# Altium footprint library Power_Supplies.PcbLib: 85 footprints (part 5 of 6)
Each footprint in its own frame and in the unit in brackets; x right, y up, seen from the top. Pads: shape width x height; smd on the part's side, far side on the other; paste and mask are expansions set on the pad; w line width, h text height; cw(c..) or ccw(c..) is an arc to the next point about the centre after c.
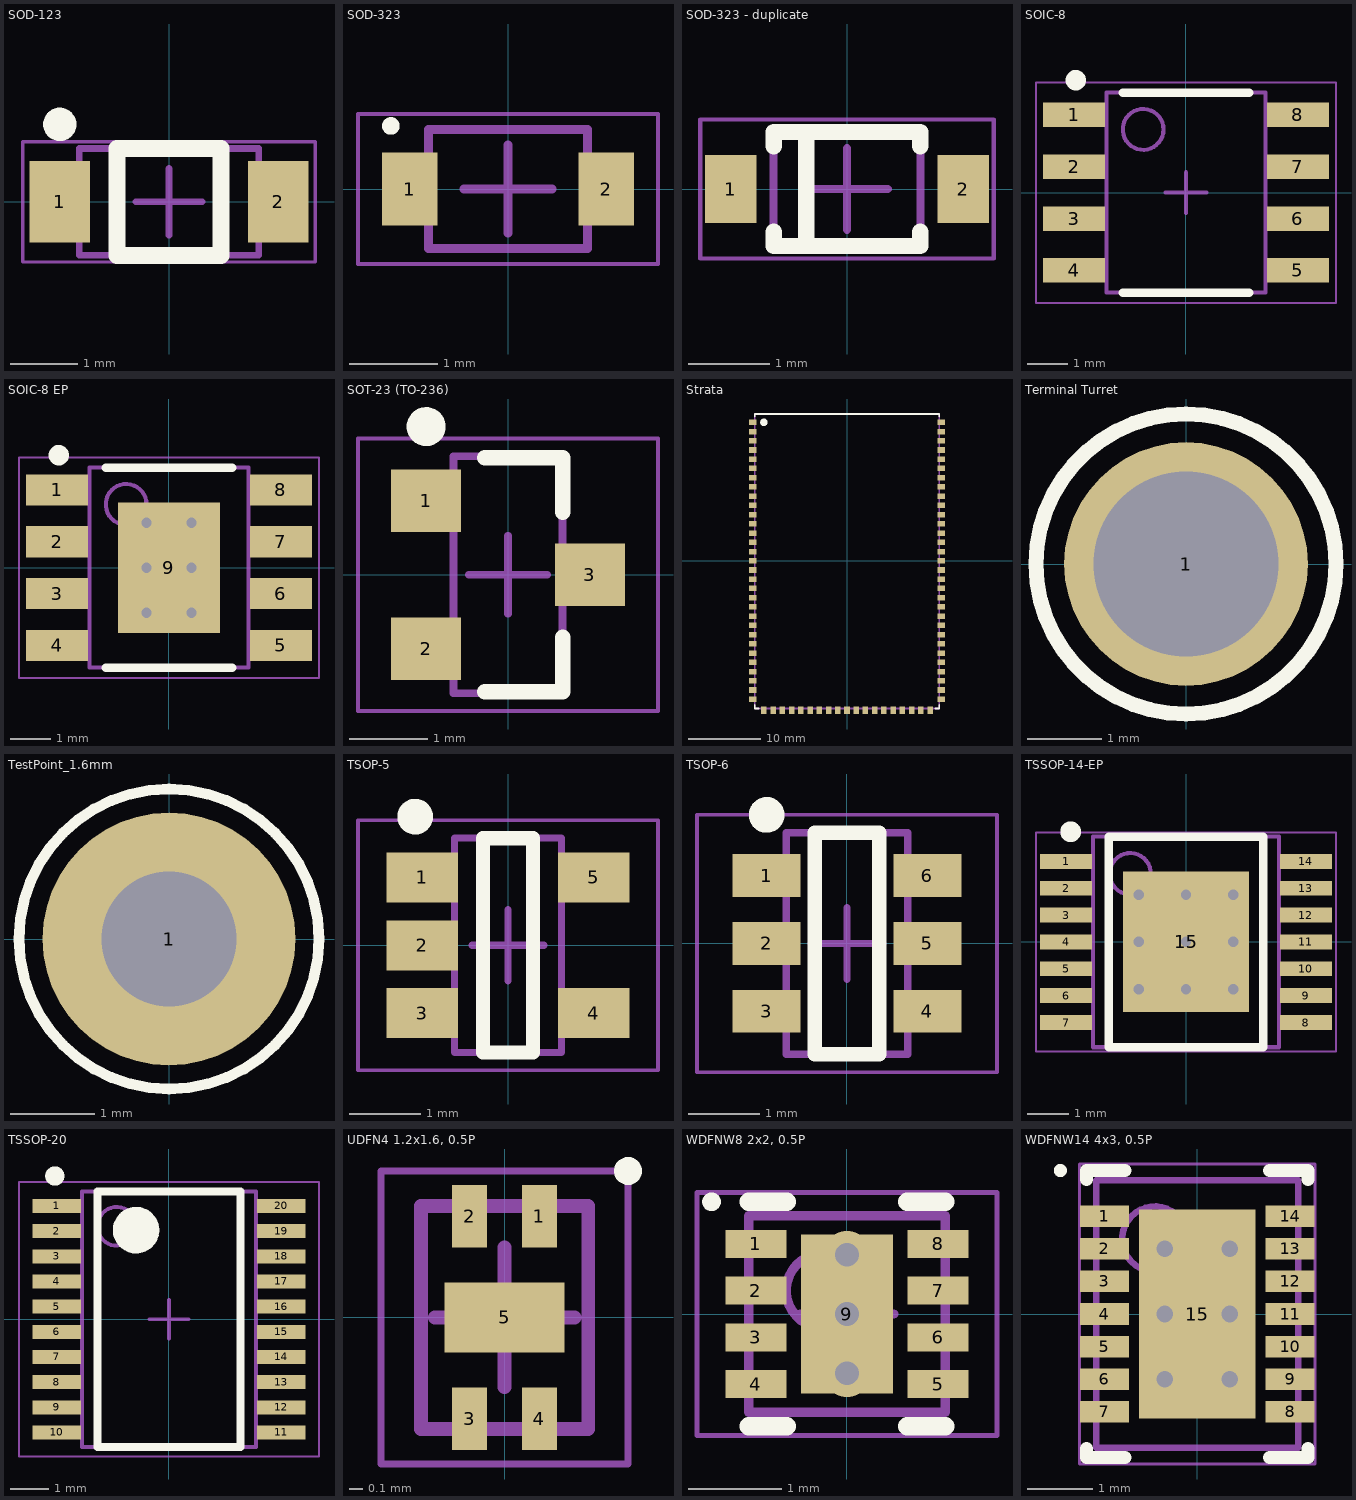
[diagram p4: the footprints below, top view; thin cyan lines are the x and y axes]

## SOD-123 [mm] "SOD, 2-Leads, Body 2.69x1.6mm"
height 1.35
pads (2):
  rect 0.91x1.22 smd: 1(-1.635,0) 2(1.635,0)
Top Overlay:
  circle w0.25: c-1.635,1.16 r0.125
  lines w0.254: -0.78,-0.8 0.78,-0.8 0.78,0.8 -0.78,0.8 -0.78,-0.8
Mechanical 13:
  lines w0.1: -1.345,-0.8 1.345,-0.8 1.345,0.8 -1.345,0.8 -1.345,-0.8
Mechanical 15:
  lines w0.05: -2.19,-0.9 2.19,-0.9 2.19,0.9 -2.19,0.9 -2.19,-0.9
  lines w0.1: -0.5,0 0.5,0 ; 0,-0.5 0,0.5
3D body "SOD123.step": height 1.27, standoff 0, extent -1.85,-0.8 1.85,0.8

## SOD-323 [mm] "SOD-323, CASE 477-02 Issue H"
height 1
pads (2):
  rect 0.63x0.83 smd: 1(-1.112,0) 2(1.112,0)
Top Overlay:
  circle w0.1: c-1.328,0.715 r0.05
Mechanical 13:
  lines w0.1: -0.9,-0.675 0.9,-0.675 0.9,0.675 -0.9,0.675 -0.9,-0.675
Mechanical 15:
  lines w0.05: -1.7,-0.85 1.7,-0.85 1.7,0.85 -1.7,0.85 -1.7,-0.85
  lines w0.1: -0.5,0 0.5,0 ; 0,-0.5 0,0.5
3D body "SOD-323.step": height 1, standoff 0, extent -1.25,-0.675 1.25,0.675

## SOD-323 - duplicate [mm] "SOD323, 2-Leads, Body 1.25x1.70mm, IPC Medium Density"
height 1
pads (2):
  rect 0.63x0.83 smd: 1(-1.425,0) 2(1.425,0)
Top Overlay:
  lines w0.2: -0.9,-0.525 -0.9,-0.7 0.9,-0.7 0.9,-0.525 ; -0.9,0.525 -0.9,0.7 0.9,0.7 0.9,0.525 ; -0.5,-0.7 -0.5,0.675
Mechanical 13:
  lines w0.1: -0.9,-0.675 -0.9,0.675 0.9,0.675 0.9,-0.675 -0.9,-0.675
Mechanical 15:
  lines w0.05: -1.8,-0.85 -1.8,0.85 1.8,0.85 1.8,-0.85 -1.8,-0.85
  lines w0.1: -0.5,0 0.5,0 ; 0,-0.5 0,0.5
3D body: height 1, standoff 0, extent -0.9,-0.675 0.9,0.675

## SOIC-8 [mm] "SOIC-8 NB, CASE 751-7, Issue AK"
height 1.75
pads (8):
  rect 1.52x0.6 smd: 1(-2.74,1.905) 2(-2.74,0.635) 3(-2.74,-0.635) 4(-2.74,-1.905) 5(2.74,-1.905) 6(2.74,-0.635) 7(2.74,0.635) 8(2.74,1.905)
Top Overlay:
  circle w0.25: c-2.7,2.755 r0.125
  lines w0.2: -1.55,-2.45 1.55,-2.45 ; -1.55,2.45 1.55,2.45
Mechanical 13:
  circle w0.1: c-1.05,1.55 r0.5
  lines w0.1: -1.95,-2.45 -1.95,2.45 1.95,2.45 1.95,-2.45 -1.95,-2.45
Mechanical 15:
  lines w0.05: -3.675,-2.7 -3.675,2.7 3.675,2.7 3.675,-2.7 -3.675,-2.7
  lines w0.1: -0.5,0 0.5,0 ; 0,-0.5 0,0.5
3D body "SOIC127P600-8N.step": height 1.75, standoff 0, extent -3,-2.45 3,2.45

## SOIC-8 EP [mm] "SOIC-8 EP, CASE 751AC, Issue C"
height 1.75
pads (9):
  rect 1.52x0.76 smd: 1(-2.74,1.905) 2(-2.74,0.635) 3(-2.74,-0.635) 4(-2.74,-1.905) 5(2.74,-1.905) 6(2.74,-0.635) 7(2.74,0.635) 8(2.74,1.905)
  rect 2.51x3.2 smd: 9(0,0)
via -0.55,1.1 diameter 0.508 hole 0.254
via 0.55,1.1 diameter 0.508 hole 0.254
via -0.55,0 diameter 0.508 hole 0.254
via 0.55,0 diameter 0.508 hole 0.254
via -0.55,-1.1 diameter 0.508 hole 0.254
via 0.55,-1.1 diameter 0.508 hole 0.254
Top Overlay:
  circle w0.25: c-2.7,2.755 r0.125
  lines w0.2: -1.55,-2.45 1.55,-2.45 ; -1.55,2.45 1.55,2.45
Mechanical 13:
  circle w0.1: c-1.05,1.55 r0.5
  lines w0.1: -1.95,-2.45 -1.95,2.45 1.95,2.45 1.95,-2.45 -1.95,-2.45
Mechanical 15:
  lines w0.05: -3.675,-2.7 -3.675,2.7 3.675,2.7 3.675,-2.7 -3.675,-2.7
  lines w0.1: -0.5,0 0.5,0 ; 0,-0.5 0,0.5
3D body "SOIC127P600-8N.step": height 1.75, standoff 0, extent -3,-2.45 3,2.45

## SOT-23 (TO-236) [mm] "SOT-23 (TO-236), CASE 318-08, Issue AS"
height 1.11
pads (3):
  rect 0.9x0.8 smd: 1(-1.05,0.95) 2(-1.05,-0.95) 3(1.05,0)
Top Overlay:
  circle w0.25: c-1.05,1.9 r0.125
  lines w0.2: -0.3,-1.5 0.7,-1.5 0.7,-0.8 ; -0.3,1.5 0.7,1.5 0.7,0.8
Mechanical 13:
  lines w0.1: -0.7,-1.52 0.7,-1.52 0.7,1.52 -0.7,1.52 -0.7,-1.52
Mechanical 15:
  lines w0.05: -1.925,-1.75 1.925,-1.75 1.925,1.75 -1.925,1.75 -1.925,-1.75
  lines w0.1: -0.5,0 0.5,0 ; 0,-0.5 0,0.5
3D body "SOT23127P600-8N.step": height 1.11, standoff 0, extent -1.32,-1.52 1.32,1.52

## Strata [mil]
pads (81):
  rect 40x30 smd: 1(-510,750) 2(-510,700) 3(-510,650) 4(-510,600) 5(-510,550) 6(-510,500) 7(-510,450) 8(-510,400) 9(-510,350) 10(-510,300) 11(-510,250) 12(-510,200) 13(-510,150) 14(-510,100) 15(-510,50) 16(-510,0) 17(-510,-50) 18(-510,-100) 19(-510,-150) 20(-510,-200) 21(-510,-250) 22(-510,-300) 23(-510,-350) 24(-510,-400) 25(-510,-450) 26(-510,-500) 27(-510,-550) 28(-510,-600) 29(-510,-650) 30(-510,-700) 31(-510,-750) 51(510,-750) 52(510,-700) 53(510,-650) 54(510,-600) 55(510,-550) 56(510,-500) 57(510,-450) 58(510,-400) 59(510,-350) 60(510,-300) 61(510,-250) 62(510,-200) 63(510,-150) 64(510,-100) 65(510,-50) 66(510,0) 67(510,50) 68(510,100) 69(510,150) 70(510,200) 71(510,250) 72(510,300) 73(510,350) 74(510,400) 75(510,450) 76(510,500) 77(510,550) 78(510,600) 79(510,650) 80(510,700) 81(510,750)
  rect 30x40 smd: 32(-450,-810) 33(-400,-810) 34(-350,-810) 35(-300,-810) 36(-250,-810) 37(-200,-810) 38(-150,-810) 39(-100,-810) 40(-50,-810) 41(0,-810) 42(50,-810) 43(100,-810) 44(150,-810) 45(200,-810) 46(250,-810) 47(300,-810) 48(350,-810) 49(400,-810) 50(450,-810)
Top Overlay:
  circle w20: c-450,750 r10
  lines w10: -500,-780 -500,-800 -480,-800 ; -500,780 -500,795 500,795 500,780 ; 480,-800 500,-800 500,-780
Mechanical 15:
  lines w10: -500,-800 500,-800 500,795 -500,795 -500,-800

## Terminal Turret [mm]
pads (1):
  round 3.3 hole 2.5: 1(0,0)
Top Overlay:
  circle w0.203: c0,0 r2.032
3D body "Terminal Turret.step": height 5.56, standoff -2.77, extent -1.587,-1.587 1.588,1.588

## TestPoint_1.6mm [mm]
pads (1):
  round 3 hole 1.6: 1(0,0)
Top Overlay:
  circle w0.127: c0,0 r1.778
3D body "TestPoint_5010.step": height 8.13, standoff -3.1, extent -1.587,-1.587 1.587,1.588

## TSOP-5 [mm] "TSOP, 5-Leads, Body 3.00x1.50mm, Pitch 0.95mm, IPC Medium Density"
height 1.1
pads (5):
  rect 1x0.7 smd: 1(-1.2,0.95) 2(-1.2,0) 3(-1.2,-0.95) 4(1.2,-0.95) 5(1.2,0.95)
Top Overlay:
  circle w0.25: c-1.3,1.8 r0.125
  lines w0.2: -0.35,-1.5 0.35,-1.5 0.35,1.5 -0.35,1.5 -0.35,-1.5
Mechanical 13:
  lines w0.1: -0.75,-1.5 -0.75,1.5 0.75,1.5 0.75,-1.5 -0.75,-1.5
Mechanical 15:
  lines w0.05: -2.1,-1.75 -2.1,1.75 2.1,1.75 2.1,-1.75 -2.1,-1.75
  lines w0.1: -0.5,0 0.5,0 ; 0,-0.5 0,0.5
3D body: height 1.1, standoff 0.01, extent -0.75,-1.5 0.75,1.5

## TSOP-6 [mm] "TSOP-6, CASE 318G-02, ISSUE V"
height 1.1
pads (6):
  rect 0.95x0.6 smd: 1(-1.125,0.95) 2(-1.125,0) 3(-1.125,-0.95) 4(1.125,-0.95) 5(1.125,0) 6(1.125,0.95)
Top Overlay:
  circle w0.25: c-1.125,1.8 r0.125
  lines w0.2: -0.45,-1.55 -0.45,1.55 0.45,1.55 0.45,-1.55 -0.45,-1.55
Mechanical 13:
  lines w0.1: -0.85,-1.55 0.85,-1.55 0.85,1.55 -0.85,1.55 -0.85,-1.55
Mechanical 15:
  lines w0.05: -2.1,-1.8 2.1,-1.8 2.1,1.8 -2.1,1.8 -2.1,-1.8
  lines w0.1: -0.5,0 0.5,0 ; 0,-0.5 0,0.5
3D body "TSOP-6.step": height 1.1, standoff 0, extent -32729.151,-32729.201 -32726.151,-32726.101

## TSSOP-14-EP [mm] "SOP, 14-Leads Exposed PAD, Body 5.1x4.5mm, Pitch 0.65mm"
height 1.2
pads (15):
  rect 1.26x0.36 smd: 1(-2.9,1.95) 2(-2.9,1.3) 3(-2.9,0.65) 4(-2.9,0) 5(-2.9,-0.65) 6(-2.9,-1.3) 7(-2.9,-1.95) 8(2.9,-1.95) 9(2.9,-1.3) 10(2.9,-0.65) 11(2.9,0) 12(2.9,0.65) 13(2.9,1.3) 14(2.9,1.95)
  rect 3.06x3.4 smd: 15(0,0)
via 0,-1.143 diameter 0.508 hole 0.254
via -1.143,-1.143 diameter 0.508 hole 0.254
via 0,0 diameter 0.508 hole 0.254
via -1.143,0 diameter 0.508 hole 0.254
via 1.143,0 diameter 0.508 hole 0.254
via 1.143,-1.143 diameter 0.508 hole 0.254
via 1.143,1.143 diameter 0.508 hole 0.254
via -1.143,1.143 diameter 0.508 hole 0.254
via 0,1.143 diameter 0.508 hole 0.254
Top Overlay:
  circle w0.25: c-2.792,2.667 r0.125
  lines w0.203: -1.87,-2.55 1.87,-2.55 1.87,2.55 -1.87,2.55 -1.87,-2.55
Mechanical 13:
  circle w0.1: c-1.35,1.65 r0.5
  lines w0.1: -2.25,-2.55 2.25,-2.55 2.25,2.55 -2.25,2.55 -2.25,-2.55
Mechanical 15:
  lines w0.05: -3.63,-2.65 -3.63,2.65 3.63,2.65 3.63,-2.65 -3.63,-2.65
  lines w0.1: -0.5,0 0.5,0 ; -0.5,0 0.5,0 ; -0.5,0 0.5,0 ; 0,-0.5 0,0.5 ; 0,-0.5 0,0.5 ; 0,-0.5 0,0.5
3D body "User Library-TSSOP14 - Copy.step": height 1.2, standoff 0, extent -3.2,-2.55 3.2,2.55

## TSSOP-20 [mm] "TSSOP, 20-Leads, Body 6.50x4.40mm, Pitch 0.65mm, IPC Medium Density"
height 1.2
pads (20):
  rect 1.26x0.36 smd: 1(-2.9,2.925) 2(-2.9,2.275) 3(-2.9,1.625) 4(-2.9,0.975) 5(-2.9,0.325) 6(-2.9,-0.325) 7(-2.9,-0.975) 8(-2.9,-1.625) 9(-2.9,-2.275) 10(-2.9,-2.925) 11(2.9,-2.925) 12(2.9,-2.275) 13(2.9,-1.625) 14(2.9,-0.975) 15(2.9,-0.325) 16(2.9,0.325) 17(2.9,0.975) 18(2.9,1.625) 19(2.9,2.275) 20(2.9,2.925)
Top Overlay:
  circle w0.6: c-0.85,2.3 r0.3
  circle w0.25: c-2.95,3.7 r0.125
  lines w0.2: -1.85,-3.3 1.85,-3.3 1.85,3.3 -1.85,3.3 -1.85,-3.3
Mechanical 13:
  circle w0.1: c-1.35,2.4 r0.5
  lines w0.1: -2.25,-3.3 2.25,-3.3 2.25,3.3 -2.25,3.3 -2.25,-3.3
Mechanical 15:
  lines w0.05: -3.875,-3.55 3.875,-3.55 3.875,3.55 -3.875,3.55 -3.875,-3.55
  lines w0.1: -0.5,0 0.5,0 ; 0,-0.5 0,0.5
3D body: height 1.2, standoff 0.05, extent -2.25,-3.3 2.25,3.3

## UDFN4 1.2x1.6, 0.5P [mm] "UDFN4 1.2x1.6, 0.5P, CASE 517CE, Issue B"
height 0.55
pads (5):
  rect 0.25x0.45 smd: 1(0.25,0.725) 2(-0.25,0.725) 3(-0.25,-0.725) 4(0.25,-0.725)
  rect 0.86x0.5 smd: 5(0,0)
Top Overlay:
  circle w0.1: c0.885,1.05 r0.05
Mechanical 13:
  lines w0.1: -0.6,-0.8 -0.6,0.8 0.6,0.8 0.6,-0.8 -0.6,-0.8
Mechanical 15:
  lines w0.05: -0.885,-1.05 -0.885,1.05 0.885,1.05 0.885,-1.05 -0.885,-1.05
  lines w0.1: -0.5,0 0.5,0 ; 0,-0.5 0,0.5
3D body "UDFN4 1.2x1.6, 0.5P .step": height 0.55, standoff 0, extent -1461835.67,1385469.75 -1461834.468,1385471.35

## WDFNW8 2x2, 0.5P [mm] "WDFNW8 2x2, 0.5P, CASE 511CL, Issue O"
height 0.8
pads (9):
  rect 0.65x0.3 smd: 1(-0.975,0.75) 2(-0.975,0.25) 3(-0.975,-0.25) 4(-0.975,-0.75) 5(0.975,-0.75) 6(0.975,-0.25) 7(0.975,0.25) 8(0.975,0.75)
  rect 0.98x1.7 smd: 9(0,0)
via 0,-0.635 diameter 0.508 hole 0.254
via 0,0.635 diameter 0.508 hole 0.254
via 0,0 diameter 0.508 hole 0.254
Top Overlay:
  circle w0.1: c-1.45,1.2 r0.05
  lines w0.2: -1.05,-1.2 -0.645,-1.2 ; -1.05,1.2 -0.645,1.2 ; 0.645,-1.2 1.05,-1.2 ; 0.645,1.2 1.05,1.2
Mechanical 13:
  circle w0.1: c-0.25,0.25 r0.4
  lines w0.1: -1.05,-1.05 -1.05,1.05 1.05,1.05 1.05,-1.05 -1.05,-1.05
Mechanical 15:
  lines w0.05: -1.605,-1.3 -1.605,1.3 1.605,1.3 1.605,-1.3 -1.605,-1.3
  lines w0.1: -0.5,0 0.5,0 ; 0,-0.5 0,0.5
3D body "WDFNW8 2x2, 0.5P.step": height 0.8, standoff 0, extent -1.051,-1.05 1.051,1.05

## WDFNW14 4x3, 0.5P [mm] "WDFNW14 4x3, 0.5P, CASE 511CM, Issue A"
height 0.8
pads (15):
  rect 0.75x0.33 smd: 1(-1.425,1.5) 2(-1.425,1) 3(-1.425,0.5) 4(-1.425,0) 5(-1.425,-0.5) 6(-1.425,-1) 7(-1.425,-1.5) 8(1.425,-1.5) 9(1.425,-1) 10(1.425,-0.5) 11(1.425,0) 12(1.425,0.5) 13(1.425,1) 14(1.425,1.5)
  rect 1.78x3.2 smd: 15(0,0)
via -0.5,1 diameter 0.508 hole 0.254
via 0.5,1 diameter 0.508 hole 0.254
via -0.5,0 diameter 0.508 hole 0.254
via 0.5,0 diameter 0.508 hole 0.254
via -0.5,-1 diameter 0.508 hole 0.254
via 0.5,-1 diameter 0.508 hole 0.254
Top Overlay:
  circle w0.1: c-2.1,2.2 r0.05
  lines w0.2: -1.7,-2.065 -1.7,-2.2 -1.11,-2.2 ; -1.7,2.065 -1.7,2.2 -1.11,2.2 ; 1.11,-2.2 1.7,-2.2 1.7,-2.065 ; 1.11,2.2 1.7,2.2 1.7,2.065
Mechanical 13:
  circle w0.1: c-0.65,1.15 r0.5
  lines w0.1: -1.55,-2.05 -1.55,2.05 1.55,2.05 1.55,-2.05 -1.55,-2.05
Mechanical 15:
  lines w0.05: -1.805,-2.3 -1.805,2.3 1.805,2.3 1.805,-2.3 -1.805,-2.3
  lines w0.1: -0.5,0 0.5,0 ; 0,-0.5 0,0.5
3D body "WDFN14.step": height 0.8, standoff 0, extent -1.551,-2.05 1.551,2.05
